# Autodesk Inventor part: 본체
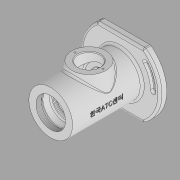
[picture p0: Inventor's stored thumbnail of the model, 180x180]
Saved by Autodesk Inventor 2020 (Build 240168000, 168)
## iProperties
Created: 2022-05
Part Number: 본체
Material: 일반
Document SubType Name: Modeling
Designer: User
Density: 1 g/cm^3
Appearance: 기본값
Author: User
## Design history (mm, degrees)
sketch "스케치1"
  geometry: L1 (57.5, 0)-(-57.5, 0); L2 (-57.5, 0)-(-57.5, 32); L3 (44.5, 32)-(44.5, 58); L4 (44.5, 58)-(54.5, 58); L5 (54.5, 58)-(54.5, 36); L6 (54.5, 36)-(57.5, 36); L7 (57.5, 36)-(57.5, 0); L8 (-49.5, 0)-(-49.5, 24); L9 (-49.5, 24)-(-46.5, 24); L10 (-46.5, 24)-(-46.5, 22.5); L11 (-46.5, 22.5)-(-35.5, 22.5); L12 (-35.5, 22.5)-(-35.5, 17.5); L13 (-35.5, 17.5)-(-33.25, 17.5); L14 (-33.25, 17.5)-(-33.25, 18.5); L15 (-33.25, 18.5)-(-31.5, 18.5); L16 (-31.5, 18.5)-(-31.5, 17.5); L17 (-31.5, 17.5)-(-20.5, 17.5); L18 (-20.5, 17.5)-(-20.5, 27); L19 (-20.5, 27)-(17.5, 27); L20 (17.5, 27)-(17.5, 17.5); L21 (17.5, 17.5)-(28.5, 17.5); L22 (28.5, 17.5)-(28.5, 15); L23 (28.5, 15)-(33.5, 15); L24 (33.5, 15)-(33.5, 11); L25 (33.5, 11)-(36.2, 11); L26 (36.2, 11)-(36.2, 15); L27 (36.2, 15)-(43.5, 15); L28 (-57.5, 32)-(44.5, 32); L29 (43.5, 15)-(43.5, 20); L30 (43.5, 20)-(57.5, 30); 2 further points
  constraints: 60 end point, 20 perpendicular, 6 point on line, 3 vertical, 2 coincident, 2 horizontal, 1 midpoint
  dimensions: "d1" = 115 distance between parallel lines of L7 L2; "d2" = 13 distance between parallel lines of L7 L3; "d4" = 3 distance between parallel lines of L7 L5; "d5" = 116 diameter of L4 L1; "d6" = 72 diameter of L6 L1; "d7" = 64 diameter of L28 L1; "d8" = 48 diameter of L9 L1; "d9" = 45 diameter of L11 L1; "d10" = 8 distance between parallel lines of L2 L8; "d11" = 3 distance of L8.end L9.end; "d13" = 22 distance between parallel lines of L2 L12; "d14" = 14 horizontal distance of L27.end L30.end; "d17" = 29 distance between parallel lines of L22 L7; "d18" = 11 distance of L20.end L21.end; "d19" = 38 distance of L18.end L19.end; "d20" = 11 distance of L16.end L17.end; "d21" = 5 distance of L22.end L23.end; "d22" = 35 diameter of L13 L1; "d23" = 54 diameter of L19 L1; "d24" = 30 diameter of L23 L1; "d25" = 22 diameter of L25 L1; "d28" = 1.75 distance of L14.end L15.end; "d29" = 37 diameter of L15 L1; "d74" = 60 diameter of L30.end L1; "d75" = 20 vertical distance of L1.start L29.end; "d76" = 7.3 distance of L26.end L27.end; "d77" = 30 diameter of L27 L1
revolve "회전1" sketch "스케치1" stored, may be unused: angle "d30" = 90 deg
sketch "스케치2"
  geometry: C1 r 32 at (0, 0) reference; 2 further points
  constraints: 1 coincident
hole "구멍1" sketch "스케치2" at (0, 0) diameter "d31" = 43.376; stored, may be unused: countersink angle "d35" = 90 deg, drill point angle "d37" = 0 deg; dims "d32" = 8, "d33" = 4, "d34" = 2, "d36" = 8
sketch "스케치3"
  geometry: L1 (-47, -60)-(47, -60); L2 (47, -60)-(47, 60); L3 (47, 60)-(-47, 60); L4 (-47, 60)-(-47, -60); L5 (-47, -60)-(47, 60); L6 (47, -60)-(-47, 60); C1 r 58 at (0, 0) reference; 5 further points
  constraints: 12 end point, 2 midpoint, 2 parallel, 1 horizontal, 1 perpendicular
  dimensions: "d40" = 94 distance of L3.end L2.end; "d41" = 120 distance of L2.end L1.end
extrude "돌출1" cut sketch "스케치3" distance "d42" = 10; taper "d43" = 0 deg
sketch "스케치4"
  geometry: L1 (-47, 33.985)-(-47, 81.985); L2 (-47, 33.985)-(-77.854, 70.755); C1 r 32 at (-47, 33.985) reference; A1 r 48 centre (-47, 33.985) between (-47, 81.985) and (-77.854, 70.755); A2 r 4 centre (-77.854, 70.755) between (-80.425, 73.82) and (-78.806, 66.87); A3 r 4 centre (-47, 81.985) between (-47, 77.985) and (-47, 85.985); A4 r 44 centre (-47, 33.985) between (-47, 77.985) and (-75.283, 67.691); A5 r 52 centre (-47, 33.985) between (-47, 85.985) and (-80.425, 73.82); A6 r 45.75 centre (-47, 33.985) between (-47, 79.735) and (-78.806, 66.87); A7 r 50.25 centre (-47, 33.985) between (-47, 84.235) and (-81.818, 70.218); A8 r 2.25 centre (-47, 81.985) between (-47, 79.735) and (-47, 84.235); 4 further points
  constraints: 17 point on circle, 8 centre point, 6 coincident, 4 end point, 3 point on line, 1 tangent, 1 vertical
  dimensions: "d44" = 96 diameter of A1; "d45" = 40 deg angle of L2 L1; "d46" = 8 diameter of A2; "d47" = 8 diameter of A3; "d48" = 2.25 radial gap between concentric circles of A1 A6; "d49" = 2.25 radial gap between concentric circles of A1 A7
extrude "돌출2" cut sketch "스케치4" extent not by distance; stored distance "d50" = 0; taper "d51" = 0 deg
extrude "돌출3" cut sketch "스케치4" distance "d52" = 4.4; taper "d53" = 0 deg
extrude "돌출4" cut sketch "스케치4" extent not by distance; stored distance "d54" = 0; taper "d55" = 0 deg
node "작업 평면1"
chamfer "모따기2" distance "d78" = 0.7; stored, may be unused: second distance "d79" = 2, angle "d80" = 30 deg
sketch "스케치7"
  geometry: L1 (-57.5, -32)-(-57.5, 32) reference; C1 r 25 at (-1.5, 0); 1 further point
  constraints: 1 centre point, 1 horizontal alignment
  dimensions: "d83" = 50 diameter of C1; "d84" = 56 distance from line of C1.centre L1
extrude "돌출6" join sketch "스케치7" stored distance "d85" = 10; taper "d86" = 10 deg
sketch "스케치8"
  geometry: C1 r 25 at (0, 0) reference; C2 r 16 at (0, 0); 1 further point
  constraints: 1 centre point, 1 coincident
  dimensions: "d87" = 32 diameter of C2
extrude "돌출7" cut sketch "스케치8" distance "d88" = 25; taper "d89" = 0 deg
chamfer "모따기3" distance "d90" = 1; stored, may be unused: second distance "d91" = 2, angle "d92" = 30 deg
fillet "모깎기1" dims "d93" = 2
chamfer "모따기4" distance "d95" = 1; stored, may be unused: second distance "d96" = 2, angle "d97" = 30 deg
fillet "모깎기3" dims "d98" = 0.5
fillet "모깎기4" dims "d99" = 0.6
fillet "모깎기5" dims "d100" = 3
sketch "스케치9"
  geometry: L1 (0, 0)-(0, -20.5); C1 r 25 at (0, 0) reference; 2 further points
  constraints: 2 end point, 1 coincident, 1 vertical
  dimensions: "d102" = 20.5 distance of L1.start L1.end
hole "구멍3" sketch "스케치9" at (0, -20.5) diameter "d103" = 2.459; stored, may be unused: countersink angle "d107" = 90 deg, drill point angle "d109" = 118 deg; dims "d104" = 6, "d105" = 4, "d106" = 2, "d108" = 8
node "작업 평면2"
sketch "스케치10"
  geometry: L1 (41.299, -14.637)-(-39.299, -14.637); L2 (-39.299, -14.637)-(-39.299, 14.637); L3 (-39.299, 14.637)-(41.299, 14.637); L4 (41.299, 14.637)-(41.299, -14.637); L5 (41.299, -14.637)-(-39.299, 14.637); L6 (41.299, 14.637)-(-39.299, -14.637); L7 (-61, 47)-(-61, -47) reference; 3 further points
  constraints: 4 end point, 2 midpoint, 1 horizontal alignment, 2 other
  dimensions: "d113" = 62 distance from line of point (1, 0) L7
feature "엠보싱1" sketch "스케치10" dims "d1" = 115, "d2" = 13, "d4" = 3, "d5" = 116, "d6" = 72, "d7" = 64, "d8" = 48, "d9" = 45, "d10" = 8, "d11" = 3, "d13" = 22, "d14" = 14, "d17" = 29, "d18" = 11, "d19" = 38, "d20" = 11, "d21" = 5, "d22" = 35, "d23" = 54, "d24" = 30, "d25" = 22, "d28" = 1.75, "d29" = 37, "d74" = 60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
fillet "모깎기6" dims "d116" = 3
fillet "모깎기7" dims "d117" = 3
fillet "모깎기8" dims "d118" = 3
fillet "모깎기9" dims "d119" = 3
chamfer "모따기5" distance "d120" = 1; stored, may be unused: second distance "d121" = 2, angle "d122" = 30 deg
node "솔리드1"
pattern_circular "원형 패턴1" dims angle "d57" = 360 deg
pattern_circular "원형 패턴2" dims angle "d111" = 360 deg
node "투영된 루프1"
feature "A9D066F2-1C7D-4E18-AEED-F7BC21143FA4" dims "d103" = 2.459, "d104" = 6, "d105" = 4, "d106" = 2, "d107" = 90 deg, "d108" = 8, "d109" = 118 deg
other parameters: "d59" = -38
